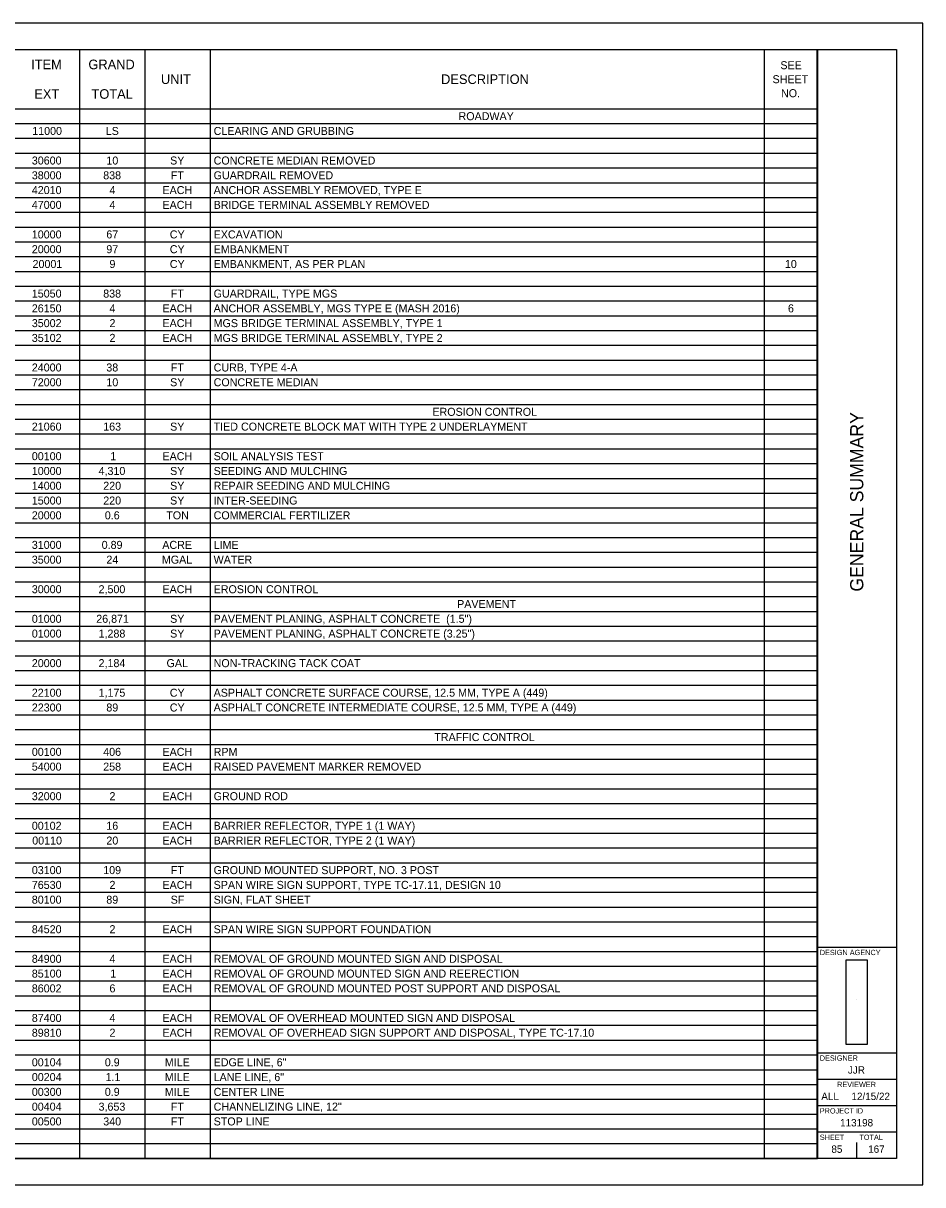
# Model space of a CAD drawing. Extents: x 0 to 34, y 0 to 22.
# Drawn here: x 16.97 to 34, y 0 to 22 of the extents above; entities that cross this region are included whole.
import ezdxf

# ---------------------------------------------------------------- set-up
doc = ezdxf.new("R2010")
doc.units = 0
for name, color, linetype in [('SH_Border', 7, 'Continuous'), ('SH_Cut_Line', 7, 'Continuous'), ('SH_Data', 7, 'Continuous'), ('SH_Text', 7, 'Continuous')]:
    doc.layers.add(name, color=color, linetype=linetype)

msp = doc.modelspace()

# ---------------------------------------------------------------- linework, layer by layer
at = {"layer": 'SH_Border'}
for p, q in [((32, 0.5), (32, 21.5)), ((32, 4.5), (33.5, 4.5)), ((32, 2.5), (33.5, 2.5)), ((32, 2), (33.5, 2)), ((32, 1.5), (33.5, 1.5)), ((32, 1), (33.5, 1))]:
    msp.add_line(p, q, dxfattribs=at)
msp.add_lwpolyline([(1.5, 21.5), (33.5, 21.5), (33.5, 0.5), (1.5, 0.5)], close=True, dxfattribs=at)
at = {"layer": 'SH_Cut_Line'}
msp.add_lwpolyline([(0, 0), (34, 0), (34, 22), (0, 22)], close=True, dxfattribs=at)
at = {"layer": 'SH_Data'}
for p, q in [((32.75, 3.5), (32.75, 3.5)), ((32.375, 0.675), (32.375, 0.675)), ((32.75, 0.5), (32.75, 0.8))]:
    msp.add_line(p, q, dxfattribs=at)
at = {"layer": 'SH_Text'}
for p, q in [((1.5, 21.5), (32.004, 21.5)), ((18.036, 21.5), (18.036, 0.5)), ((19.272, 21.5), (19.272, 0.5)), ((20.507, 21.5), (20.507, 0.5)), ((30.999, 21.5), (30.999, 0.5)), ((32.004, 21.5), (32.004, 0.5)), ((1.5, 20.38), (32.004, 20.38)), ((1.5, 20.1), (32.004, 20.1)), ((1.5, 19.82), (32.004, 19.82)), ((1.5, 19.54), (32.004, 19.54)), ((1.5, 19.26), (32.004, 19.26)), ((1.5, 18.98), (32.004, 18.98)), ((1.5, 18.7), (32.004, 18.7)), ((1.5, 18.42), (32.004, 18.42)), ((1.5, 18.14), (32.004, 18.14)), ((1.5, 17.86), (32.004, 17.86)), ((1.5, 17.58), (32.004, 17.58)), ((1.5, 17.3), (32.004, 17.3)), ((1.5, 17.02), (32.004, 17.02)), ((1.5, 16.74), (32.004, 16.74)), ((1.5, 16.46), (32.004, 16.46)), ((1.5, 16.18), (32.004, 16.18)), ((1.5, 15.9), (32.004, 15.9)), ((1.5, 15.62), (32.004, 15.62)), ((1.5, 15.34), (32.004, 15.34)), ((1.5, 15.06), (32.004, 15.06)), ((1.5, 14.78), (32.004, 14.78)), ((1.5, 14.5), (32.004, 14.5)), ((1.5, 14.22), (32.004, 14.22)), ((1.5, 13.94), (32.004, 13.94)), ((1.5, 13.66), (32.004, 13.66)), ((1.5, 13.38), (32.004, 13.38)), ((1.5, 13.1), (32.004, 13.1)), ((1.5, 12.82), (32.004, 12.82)), ((1.5, 12.54), (32.004, 12.54)), ((1.5, 12.26), (32.004, 12.26)), ((1.5, 11.98), (32.004, 11.98)), ((1.5, 11.7), (32.004, 11.7)), ((1.5, 11.42), (32.004, 11.42)), ((1.5, 11.14), (32.004, 11.14)), ((1.5, 10.86), (32.004, 10.86)), ((1.5, 10.58), (32.004, 10.58)), ((1.5, 10.3), (32.004, 10.3)), ((1.5, 10.02), (32.004, 10.02)), ((1.5, 9.74), (32.004, 9.74)), ((1.5, 9.46), (32.004, 9.46)), ((1.5, 9.18), (32.004, 9.18)), ((1.5, 8.9), (32.004, 8.9)), ((1.5, 8.62), (32.004, 8.62)), ((1.5, 8.34), (32.004, 8.34)), ((1.5, 8.06), (32.004, 8.06)), ((1.5, 7.78), (32.004, 7.78)), ((1.5, 7.5), (32.004, 7.5)), ((1.5, 7.22), (32.004, 7.22)), ((1.5, 6.94), (32.004, 6.94)), ((1.5, 6.66), (32.004, 6.66)), ((1.5, 6.38), (32.004, 6.38)), ((1.5, 6.1), (32.004, 6.1)), ((1.5, 5.82), (32.004, 5.82)), ((1.5, 5.54), (32.004, 5.54)), ((1.5, 5.26), (32.004, 5.26)), ((1.5, 4.98), (32.004, 4.98)), ((1.5, 4.7), (32.004, 4.7)), ((1.5, 4.42), (32.004, 4.42)), ((1.5, 4.14), (32.004, 4.14)), ((1.5, 3.86), (32.004, 3.86)), ((1.5, 3.58), (32.004, 3.58)), ((1.5, 3.3), (32.004, 3.3)), ((1.5, 3.02), (32.004, 3.02)), ((1.5, 2.74), (32.004, 2.74)), ((1.5, 2.46), (32.004, 2.46)), ((1.5, 2.18), (32.004, 2.18)), ((1.5, 1.9), (32.004, 1.9)), ((1.5, 1.62), (32.004, 1.62)), ((1.5, 1.34), (32.004, 1.34)), ((1.5, 1.06), (32.004, 1.06)), ((1.5, 0.78), (32.004, 0.78)), ((1.5, 0.5), (32.004, 0.5))]:
    msp.add_line(p, q, dxfattribs=at)
msp.add_lwpolyline([(32.956, 2.664), (32.956, 4.254), (32.544, 4.254), (32.544, 2.664)], close=True, dxfattribs=at)

# ---------------------------------------------------------------- texts
at = {"layer": 'SH_Data'}
msp.add_text('GENERAL SUMMARY', height=0.25, rotation=90, dxfattribs=at).set_placement((32.875, 11.235))
for s, height, p in [('DESIGN AGENCY', 0.1, (32.05, 4.35)), ('DESIGNER', 0.1, (32.05, 2.35)), ('JJR', 0.14, (32.583, 2.105)), ('REVIEWER', 0.1, (32.378, 1.85)), ('ALL', 0.14, (32.079, 1.605)), ('12/15/22', 0.14, (32.65, 1.605)), ('PROJECT ID', 0.1, (32.05, 1.35)), ('113198', 0.14, (32.435, 1.105)), ('SHEET', 0.1, (32.05, 0.85)), ('TOTAL', 0.1, (32.8, 0.85)), ('85', 0.14, (32.27, 0.605)), ('167', 0.14, (32.966, 0.605))]:
    msp.add_text(s, height=height, dxfattribs=at).set_placement(p)
at = {"layer": 'SH_Text'}
for s, height, p in [('ITEM', 0.1818, (17.117, 21.129)), ('GRAND', 0.1818, (18.202, 21.129)), ('SEE ', 0.1515, (31.304, 21.129)), ('UNIT', 0.1818, (19.575, 20.849)), ('DESCRIPTION', 0.18184, (24.88, 20.849)), ('SHEET ', 0.1515, (31.156, 20.864)), ('EXT', 0.1818, (17.177, 20.569)), ('TOTAL', 0.1818, (18.26, 20.569)), ('NO.', 0.1515, (31.316, 20.599)), ('ROADWAY', 0.1515, (25.21, 20.164)), ('11000', 0.1515, (17.138, 19.884)), ('LS', 0.1515, (18.53, 19.884)), ('CLEARING AND GRUBBING', 0.15153, (20.573, 19.884)), ('30600', 0.1515, (17.13, 19.324)), ('10', 0.1515, (18.542, 19.324)), ('SY', 0.1515, (19.749, 19.324)), ('CONCRETE MEDIAN REMOVED', 0.15153, (20.573, 19.324)), ('38000', 0.1515, (17.13, 19.044)), ('838', 0.1515, (18.482, 19.044)), ('FT', 0.1515, (19.762, 19.044)), ('GUARDRAIL REMOVED', 0.15153, (20.573, 19.044)), ('42010', 0.1515, (17.13, 18.764)), ('4', 0.152, (18.6, 18.764)), ('EACH', 0.1515, (19.604, 18.764)), ('ANCHOR ASSEMBLY REMOVED, TYPE E', 0.15153, (20.573, 18.764)), ('47000', 0.1515, (17.13, 18.484)), ('4', 0.152, (18.6, 18.484)), ('EACH', 0.1515, (19.604, 18.484)), ('BRIDGE TERMINAL ASSEMBLY REMOVED', 0.15153, (20.573, 18.484)), ('10000', 0.1515, (17.13, 17.924)), ('67', 0.1515, (18.541, 17.924)), ('CY', 0.1515, (19.743, 17.924)), ('EXCAVATION', 0.1515, (20.573, 17.924)), ('20000', 0.1515, (17.13, 17.644)), ('97', 0.1515, (18.541, 17.644)), ('CY', 0.1515, (19.743, 17.644)), ('EMBANKMENT', 0.1515, (20.573, 17.644)), ('20001', 0.1515, (17.144, 17.364)), ('9', 0.152, (18.6, 17.364)), ('CY', 0.1515, (19.743, 17.364)), ('EMBANKMENT, AS PER PLAN', 0.15153, (20.573, 17.364)), ('10', 0.1515, (31.389, 17.364)), ('15050', 0.1515, (17.13, 16.804)), ('838', 0.1515, (18.482, 16.804)), ('FT', 0.1515, (19.762, 16.804)), ('GUARDRAIL, TYPE MGS', 0.15153, (20.573, 16.804)), ('26150', 0.1515, (17.13, 16.524)), ('4', 0.152, (18.6, 16.524)), ('EACH', 0.1515, (19.604, 16.524)), ('ANCHOR ASSEMBLY, MGS TYPE E (MASH 2016)', 0.15153, (20.573, 16.524)), ('6', 0.152, (31.447, 16.524)), ('35002', 0.1515, (17.13, 16.244)), ('2', 0.152, (18.601, 16.244)), ('EACH', 0.1515, (19.604, 16.244)), ('MGS BRIDGE TERMINAL ASSEMBLY, TYPE 1', 0.15153, (20.573, 16.244)), ('35102', 0.1515, (17.13, 15.964)), ('2', 0.152, (18.601, 15.964)), ('EACH', 0.1515, (19.604, 15.964)), ('MGS BRIDGE TERMINAL ASSEMBLY, TYPE 2', 0.15153, (20.573, 15.964)), ('24000', 0.1515, (17.13, 15.404)), ('38', 0.1515, (18.541, 15.404)), ('FT', 0.1515, (19.762, 15.404)), ('CURB, TYPE 4-A', 0.15153, (20.573, 15.404)), ('72000', 0.1515, (17.13, 15.124)), ('10', 0.1515, (18.542, 15.124)), ('SY', 0.1515, (19.749, 15.124)), ('CONCRETE MEDIAN', 0.15153, (20.573, 15.124)), ('EROSION CONTROL', 0.15153, (24.715, 14.564)), ('21060', 0.1515, (17.13, 14.284)), ('163', 0.1515, (18.482, 14.284)), ('SY', 0.1515, (19.749, 14.284)), ('TIED CONCRETE BLOCK MAT WITH TYPE 2 UNDERLAYMENT', 0.15153, (20.573, 14.284)), ('00100', 0.1515, (17.13, 13.724)), ('1', 0.152, (18.615, 13.724)), ('EACH', 0.1515, (19.604, 13.724)), ('SOIL ANALYSIS TEST', 0.15153, (20.573, 13.724)), ('10000', 0.1515, (17.13, 13.444)), ('4,310', 0.1515, (18.394, 13.444)), ('SY', 0.1515, (19.749, 13.444)), ('SEEDING AND MULCHING', 0.15153, (20.573, 13.444)), ('14000', 0.1515, (17.13, 13.164)), ('220', 0.1515, (18.483, 13.164)), ('SY', 0.1515, (19.749, 13.164)), ('REPAIR SEEDING AND MULCHING', 0.15153, (20.573, 13.164)), ('15000', 0.1515, (17.13, 12.884)), ('220', 0.1515, (18.483, 12.884)), ('SY', 0.1515, (19.749, 12.884)), ('INTER-SEEDING', 0.15153, (20.573, 12.884)), ('20000', 0.1515, (17.13, 12.604)), ('0.6', 0.1515, (18.512, 12.604)), ('TON', 0.1515, (19.676, 12.604)), ('COMMERCIAL FERTILIZER', 0.15153, (20.573, 12.604)), ('31000', 0.1515, (17.13, 12.044)), ('0.89', 0.1515, (18.453, 12.044)), ('ACRE', 0.1515, (19.601, 12.044)), ('LIME', 0.1515, (20.573, 12.044)), ('35000', 0.1515, (17.13, 11.764)), ('24', 0.1515, (18.542, 11.764)), ('MGAL', 0.1515, (19.593, 11.764)), ('WATER', 0.1515, (20.573, 11.764)), ('30000', 0.1515, (17.13, 11.204)), ('2,500', 0.1515, (18.394, 11.204)), ('EACH', 0.1515, (19.604, 11.204)), ('EROSION CONTROL', 0.15153, (20.573, 11.204)), ('PAVEMENT', 0.1515, (25.183, 10.924)), ('01000', 0.1515, (17.13, 10.644)), ('26,871', 0.1515, (18.35, 10.644)), ('SY', 0.1515, (19.749, 10.644)), ('PAVEMENT PLANING, ASPHALT CONCRETE  (1.5")', 0.15153, (20.573, 10.644)), ('01000', 0.1515, (17.13, 10.364)), ('1,288', 0.1515, (18.394, 10.364)), ('SY', 0.1515, (19.749, 10.364)), ('PAVEMENT PLANING, ASPHALT CONCRETE (3.25")', 0.15153, (20.573, 10.364)), ('20000', 0.1515, (17.13, 9.804)), ('2,184', 0.1515, (18.394, 9.804)), ('GAL', 0.1515, (19.681, 9.804)), ('NON-TRACKING TACK COAT', 0.15153, (20.573, 9.804)), ('22100', 0.1515, (17.13, 9.244)), ('1,175', 0.1515, (18.394, 9.244)), ('CY', 0.1515, (19.743, 9.244)), ('ASPHALT CONCRETE SURFACE COURSE, 12.5 MM, TYPE A (449)', 0.15153, (20.573, 9.244)), ('22300', 0.1515, (17.13, 8.964)), ('89', 0.1515, (18.541, 8.964)), ('CY', 0.1515, (19.743, 8.964)), ('ASPHALT CONCRETE INTERMEDIATE COURSE, 12.5 MM, TYPE A (449)', 0.15153, (20.573, 8.964)), ('TRAFFIC CONTROL', 0.15153, (24.751, 8.404)), ('00100', 0.1515, (17.13, 8.124)), ('406', 0.1515, (18.482, 8.124)), ('EACH', 0.1515, (19.604, 8.124)), ('RPM', 0.1515, (20.573, 8.124)), ('54000', 0.1515, (17.13, 7.844)), ('258', 0.1515, (18.482, 7.844)), ('EACH', 0.1515, (19.604, 7.844)), ('RAISED PAVEMENT MARKER REMOVED', 0.15153, (20.573, 7.844)), ('32000', 0.1515, (17.13, 7.284)), ('2', 0.152, (18.601, 7.284)), ('EACH', 0.1515, (19.604, 7.284)), ('GROUND ROD', 0.1515, (20.573, 7.284)), ('00102', 0.1515, (17.13, 6.724)), ('16', 0.1515, (18.541, 6.724)), ('EACH', 0.1515, (19.604, 6.724)), ('BARRIER REFLECTOR, TYPE 1 (1 WAY)', 0.15153, (20.573, 6.724)), ('BARRIER REFLECTOR, TYPE 2 (1 WAY)', 0.15153, (20.573, 6.444)), ('00110', 0.1515, (17.138, 6.444)), ('20', 0.1515, (18.542, 6.444)), ('EACH', 0.1515, (19.604, 6.444)), ('03100', 0.1515, (17.13, 5.884)), ('109', 0.1515, (18.482, 5.884)), ('FT', 0.1515, (19.762, 5.884)), ('GROUND MOUNTED SUPPORT, NO. 3 POST', 0.15153, (20.573, 5.884)), ('76530', 0.1515, (17.13, 5.604)), ('2', 0.152, (18.601, 5.604)), ('EACH', 0.1515, (19.604, 5.604)), ('SPAN WIRE SIGN SUPPORT, TYPE TC-17.11, DESIGN 10', 0.15153, (20.573, 5.604)), ('80100', 0.1515, (17.13, 5.324)), ('89', 0.1515, (18.541, 5.324)), ('SF', 0.1515, (19.759, 5.324)), ('SIGN, FLAT SHEET', 0.15153, (20.573, 5.324)), ('84520', 0.1515, (17.13, 4.764)), ('2', 0.152, (18.601, 4.764)), ('EACH', 0.1515, (19.604, 4.764)), ('SPAN WIRE SIGN SUPPORT FOUNDATION', 0.15153, (20.573, 4.764)), ('84900', 0.1515, (17.13, 4.204)), ('4', 0.152, (18.6, 4.204)), ('EACH', 0.1515, (19.604, 4.204)), ('REMOVAL OF GROUND MOUNTED SIGN AND DISPOSAL', 0.15153, (20.573, 4.204)), ('85100', 0.1515, (17.13, 3.924)), ('1', 0.152, (18.615, 3.924)), ('EACH', 0.1515, (19.604, 3.924)), ('REMOVAL OF GROUND MOUNTED SIGN AND REERECTION', 0.15153, (20.573, 3.924)), ('86002', 0.1515, (17.13, 3.644)), ('6', 0.152, (18.6, 3.644)), ('EACH', 0.1515, (19.604, 3.644)), ('REMOVAL OF GROUND MOUNTED POST SUPPORT AND DISPOSAL', 0.15153, (20.573, 3.644)), ('87400', 0.1515, (17.13, 3.084)), ('4', 0.152, (18.6, 3.084)), ('EACH', 0.1515, (19.604, 3.084)), ('REMOVAL OF OVERHEAD MOUNTED SIGN AND DISPOSAL', 0.15153, (20.573, 3.084)), ('89810', 0.1515, (17.13, 2.804)), ('2', 0.152, (18.601, 2.804)), ('EACH', 0.1515, (19.604, 2.804)), ('REMOVAL OF OVERHEAD SIGN SUPPORT AND DISPOSAL, TYPE TC-17.10', 0.15153, (20.573, 2.804)), ('00104', 0.1515, (17.13, 2.244)), ('0.9', 0.1515, (18.512, 2.244)), ('MILE', 0.1515, (19.648, 2.244)), ('EDGE LINE, 6"', 0.15153, (20.573, 2.244)), ('00204', 0.1515, (17.13, 1.964)), ('1.1', 0.1515, (18.526, 1.964)), ('MILE', 0.1515, (19.648, 1.964)), ('LANE LINE, 6"', 0.15153, (20.573, 1.964)), ('00300', 0.1515, (17.13, 1.684)), ('0.9', 0.1515, (18.512, 1.684)), ('MILE', 0.1515, (19.648, 1.684)), ('CENTER LINE', 0.15153, (20.573, 1.684)), ('00404', 0.1515, (17.13, 1.404)), ('3,653', 0.1515, (18.394, 1.404)), ('FT', 0.1515, (19.762, 1.404)), ('CHANNELIZING LINE, 12"', 0.15153, (20.573, 1.404)), ('00500', 0.1515, (17.13, 1.124)), ('340', 0.1515, (18.483, 1.124)), ('FT', 0.1515, (19.762, 1.124)), ('STOP LINE', 0.1515, (20.573, 1.124))]:
    msp.add_text(s, height=height, dxfattribs=at).set_placement(p)

doc.saveas('drawing.dxf')
